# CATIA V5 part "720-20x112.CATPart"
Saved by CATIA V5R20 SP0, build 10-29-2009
Part number: 720-20x112
Definition: NONE
Nomenclature: 720-20x112
Source: Unknown
Description: 720-20x112
Bounding box of the stored display mesh (mm): x 0 to 112, y -10 to 10, z -10 to 10
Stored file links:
  C:\Users\Utente\Desktop\IO LAVORO\3D X SITO CF\X SITO\720\720-20x112.CATPart
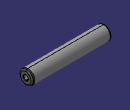
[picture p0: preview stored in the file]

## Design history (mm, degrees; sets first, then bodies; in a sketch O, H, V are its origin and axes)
Body1 "720-20x112" (main body)
  Solid1: solid without history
